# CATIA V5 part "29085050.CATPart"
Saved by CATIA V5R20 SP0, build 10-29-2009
Part number: 29085050
Definition: NONE
Nomenclature: 29085050
Source: Unknown
Description: 29085050
Bounding box of the stored display mesh (mm): x -25 to 44.548, y -56.5 to 91.048, z -46.5 to 46.5
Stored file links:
  C:\Users\Utente\Desktop\IO LAVORO\3D X SITO CF\X SITO\PLASTICA\RF1\29085050.CATPart
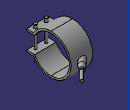
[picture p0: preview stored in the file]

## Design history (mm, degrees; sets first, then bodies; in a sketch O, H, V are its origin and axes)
Body1 "29085050" (main body)
  Solid1: solid without history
